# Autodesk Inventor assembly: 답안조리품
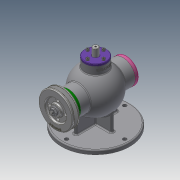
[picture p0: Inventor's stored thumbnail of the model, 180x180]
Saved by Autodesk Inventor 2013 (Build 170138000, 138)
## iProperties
Created: 2020-08
Part Number: 답안조리품
Document SubType Name: Assembly
Designer: user
Author: user
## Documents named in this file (18)
- C:\Users\user\Desktop\거위\답안조리품.iam
- C:\Users\user\Desktop\거위\700806V1039.ipt
- C:\Users\user\Desktop\거위\Ű 3x3x12.ipt
- C:\Users\user\Desktop\거위\V-벨트풀리.ipt
- C:\Users\user\Desktop\거위\너트 M8.ipt
- C:\Users\user\Desktop\거위\뒤커버.ipt
- C:\Users\user\Desktop\거위\멈춤링 15x1.ipt
- C:\Users\user\Desktop\거위\멈춤링 35x1.6.ipt
- 멈춤링 35x1.6.ipt
- C:\Users\user\Desktop\거위\베어링 6202.ipt
- 베어링 6202.ipt
- C:\Users\user\Desktop\거위\볼트 M4.ipt
- C:\Users\user\Desktop\거위\상부커버.ipt
- C:\Users\user\Desktop\거위\슬라이드.ipt
- C:\Users\user\Desktop\거위\앞커버.ipt
- C:\Users\user\Desktop\거위\오일 실 15 30 7.ipt
- C:\Users\user\Desktop\거위\칼라.ipt
- C:\Users\user\Desktop\거위\편심축.ipt
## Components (3 placed, 3 different names)
1. 700806V1039:1
2. Ű 3x3x12:1
3. V-벨트풀리:1
